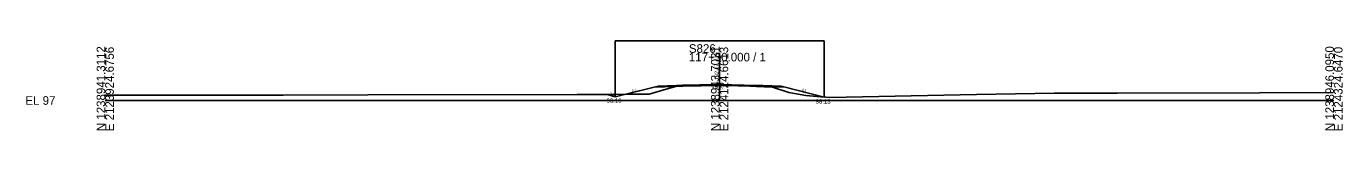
# Model space of a CAD drawing. Extents: x 2119282 to 2119710, y 1215030 to 1220057.
# Drawn here: x 2119281.9 to 2119710.4, y 1216030.1 to 1216059.3 of the extents above; entities that cross this region are included whole.
import ezdxf

# ---------------------------------------------------------------- set-up
doc = ezdxf.new("R2010")
doc.units = 0
for name, color, linetype in [('XS_CELL', 7, 'Continuous'), ('XS_M_DITCH', 7, 'Continuous'), ('XS_M_SHAPES_EARTHWORK', 7, 'Continuous'), ('XS_P_FINISHED_GRADE', 7, 'Continuous'), ('XS_P_FINISHED_GRADE_ELEV_TX', 7, 'Continuous'), ('XS_P_SUBGRADE_GRANULAR', 7, 'Continuous'), ('XS_P_SUBGRADE_PAVEMENT', 7, 'Continuous'), ('XS_P_TX_DCH', 7, 'Continuous'), ('XS_P_TX_FS_BS', 7, 'Continuous'), ('XS_X_GROUND', 7, 'Continuous'), ('XS_X_GROUND_TX', 7, 'Continuous')]:
    doc.layers.add(name, color=color, linetype=linetype)

msp = doc.modelspace()

# ---------------------------------------------------------------- linework, layer by layer
at = {"layer": 'XS_CELL'}
for p, q in [((2119507.6, 1216039.8), (2119507.6, 1216055.33)), ((2119307.6, 1216039.8), (2119507.6, 1216039.8)), ((2119507.6, 1216039.8), (2119707.6, 1216039.8))]:
    msp.add_line(p, q, dxfattribs=at)
at = {"layer": 'XS_M_DITCH'}
for p, q in [((2119473.6, 1216040.96), (2119473.6, 1216059.26)), ((2119473.6, 1216059.26), (2119541.68, 1216059.26)), ((2119541.68, 1216040.93), (2119541.68, 1216059.26))]:
    msp.add_line(p, q, dxfattribs=at)
at = {"layer": 'XS_M_SHAPES_EARTHWORK'}
for p, q in [((2119486.25, 1216044.12), (2119477.04, 1216041.82)), ((2119484.68, 1216041.89), (2119490.19, 1216043.46)), ((2119493.17, 1216044.39), (2119486.25, 1216044.12)), ((2119490.19, 1216043.46), (2119493.39, 1216044.4)), ((2119493.39, 1216044.4), (2119493.17, 1216044.39)), ((2119494.09, 1216044.6), (2119493.39, 1216044.4)), ((2119493.39, 1216044.4), (2119495.6, 1216044.44)), ((2119495.03, 1216044.7), (2119494.09, 1216044.6)), ((2119495.32, 1216044.73), (2119495.03, 1216044.7)), ((2119495.6, 1216044.75), (2119495.32, 1216044.73)), ((2119495.6, 1216044.73), (2119495.32, 1216044.73)), ((2119495.32, 1216044.73), (2119495.6, 1216044.73)), ((2119495.6, 1216044.73), (2119495.6, 1216044.75)), ((2119522.04, 1216044.39), (2119519.6, 1216044.44)), ((2119519.6, 1216044.44), (2119519.6, 1216044.39)), ((2119519.6, 1216044.39), (2119522.14, 1216044.2)), ((2119528.95, 1216044.12), (2119522.04, 1216044.39)), ((2119522.14, 1216044.2), (2119524.78, 1216044.1)), ((2119524.78, 1216044.1), (2119530.19, 1216042.44)), ((2119541.68, 1216040.93), (2119528.95, 1216044.12)), ((2119473.67, 1216041.78), (2119471.15, 1216041.77)), ((2119471.15, 1216041.77), (2119473.6, 1216040.96)), ((2119473.6, 1216040.96), (2119477.04, 1216041.82)), ((2119477.04, 1216041.82), (2119473.67, 1216041.78)), ((2119477.04, 1216041.82), (2119484.68, 1216041.89)), ((2119530.19, 1216042.44), (2119535.63, 1216041.47)), ((2119535.63, 1216041.47), (2119541.68, 1216040.93))]:
    msp.add_line(p, q, dxfattribs=at)
msp.add_lwpolyline([(2119495.6, 1216044.44), (2119495.6, 1216044.44), (2119495.6, 1216044.73)], dxfattribs=at)
at = {"layer": 'XS_P_FINISHED_GRADE'}
for p, q in [((2119487.6, 1216044.45), (2119473.6, 1216040.96)), ((2119493.6, 1216044.69), (2119487.6, 1216044.45)), ((2119495.6, 1216044.73), (2119493.6, 1216044.69)), ((2119507.6, 1216044.97), (2119495.6, 1216044.73)), ((2119507.6, 1216044.97), (2119519.6, 1216044.73)), ((2119519.6, 1216044.73), (2119521.6, 1216044.69)), ((2119521.6, 1216044.69), (2119527.6, 1216044.45)), ((2119527.6, 1216044.45), (2119541.68, 1216040.93)), ((2119473.6, 1216040.96), (2119471.15, 1216041.77))]:
    msp.add_line(p, q, dxfattribs=at)
at = {"layer": 'XS_P_SUBGRADE_GRANULAR'}
for p, q in [((2119493.17, 1216044.39), (2119486.25, 1216044.12)), ((2119522.04, 1216044.39), (2119528.95, 1216044.12))]:
    msp.add_line(p, q, dxfattribs=at)
at = {"layer": 'XS_P_SUBGRADE_PAVEMENT'}
for p, q in [((2119493.6, 1216044.69), (2119493.17, 1216044.39)), ((2119495.61, 1216044.44), (2119493.17, 1216044.39)), ((2119507.6, 1216044.68), (2119495.61, 1216044.44)), ((2119507.6, 1216044.68), (2119519.6, 1216044.44)), ((2119519.6, 1216044.44), (2119522.04, 1216044.39)), ((2119521.6, 1216044.69), (2119522.04, 1216044.39))]:
    msp.add_line(p, q, dxfattribs=at)
at = {"layer": 'XS_X_GROUND'}
for p, q in [((2119484.68, 1216041.89), (2119490.19, 1216043.46)), ((2119490.19, 1216043.46), (2119494.09, 1216044.6)), ((2119494.09, 1216044.6), (2119495.03, 1216044.7)), ((2119495.03, 1216044.7), (2119495.67, 1216044.75)), ((2119495.67, 1216044.75), (2119506.59, 1216044.96)), ((2119506.59, 1216044.96), (2119507.6, 1216044.97)), ((2119507.6, 1216044.97), (2119508.64, 1216044.93)), ((2119508.64, 1216044.93), (2119519.58, 1216044.39)), ((2119519.58, 1216044.39), (2119522.14, 1216044.2)), ((2119522.14, 1216044.2), (2119524.78, 1216044.1)), ((2119524.78, 1216044.1), (2119530.19, 1216042.44)), ((2119307.37, 1216041.54), (2119344, 1216041.55)), ((2119344, 1216041.55), (2119365.47, 1216041.58)), ((2119365.47, 1216041.58), (2119393.12, 1216041.63)), ((2119393.12, 1216041.63), (2119461.19, 1216041.75)), ((2119461.19, 1216041.75), (2119473.67, 1216041.78)), ((2119473.67, 1216041.78), (2119484.68, 1216041.89)), ((2119530.19, 1216042.44), (2119535.63, 1216041.47)), ((2119535.63, 1216041.47), (2119543.49, 1216040.77)), ((2119543.49, 1216040.77), (2119591.29, 1216041.71)), ((2119591.29, 1216041.71), (2119616.68, 1216042.23)), ((2119616.68, 1216042.23), (2119637.18, 1216042.22)), ((2119637.18, 1216042.22), (2119683.37, 1216042.3)), ((2119683.37, 1216042.3), (2119707.37, 1216042.42))]:
    msp.add_line(p, q, dxfattribs=at)

# ---------------------------------------------------------------- texts
at = {"layer": 'XS_CELL'}
for s, p in [('N 1238941.3112', (2119307.6, 1216029.8)), ('E 2123924.6756', (2119310.4, 1216029.8)), ('N 1238943.7031', (2119507.6, 1216029.8)), ('E 2124124.6613', (2119510.4, 1216029.8)), ('N 1238946.0950', (2119707.6, 1216029.8)), ('E 2124324.6470', (2119710.4, 1216029.8))]:
    msp.add_text(s, height=2.8, rotation=90, dxfattribs=at).set_placement(p)
for s, p in [('S826', (2119497.6, 1216055.33)), ('117+50.000 / 1', (2119497.6, 1216052.53)), ('EL 97', (2119281.6, 1216038.4))]:
    msp.add_text(s, height=2.8, dxfattribs=at).set_placement(p)
at = {"layer": 'XS_P_FINISHED_GRADE_ELEV_TX'}
msp.add_text('102.17', height=1.25, rotation=90, dxfattribs=at).set_placement((2119507.22, 1216046.52))
at = {"layer": 'XS_P_TX_DCH'}
for s, p in [('98.16', (2119470.82, 1216039.05)), ('98.13', (2119538.89, 1216038.8))]:
    msp.add_text(s, height=1.4, dxfattribs=at).set_placement(p)
at = {"layer": 'XS_P_TX_FS_BS'}
for s, rotation, p in [('4:1', 14.015, (2119479.11, 1216042.57)), ('4:1', 345.9638, (2119534.27, 1216042.94)), ('3:1', 341.5921, (2119471.67, 1216041.72))]:
    msp.add_text(s, height=0.8, rotation=rotation, dxfattribs=at).set_placement(p)
at = {"layer": 'XS_X_GROUND_TX'}
msp.add_text('102.17', height=1, dxfattribs=at).set_placement((2119504.78, 1216043.48))

doc.saveas('drawing.dxf')
